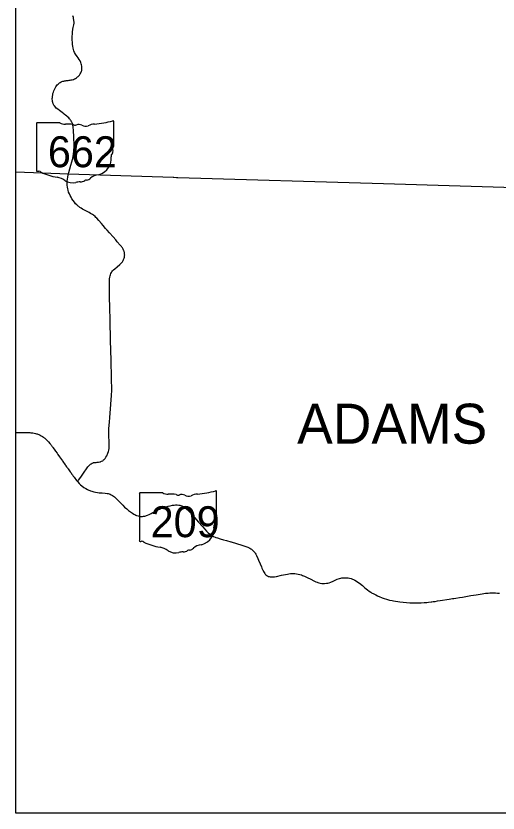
# Model space of a CAD drawing. Extents: x -12.1 to 34, y 0 to 22.
# Drawn here: x -12.146 to -10.219, y 10.977 to 14.162 of the extents above; entities that cross this region are included whole.
import ezdxf

# ---------------------------------------------------------------- set-up
doc = ezdxf.new("R2010")
doc.units = 0
for name, color, linetype in [('GM_X_State_Location', 7, 'Continuous'), ('GM_X_State_Route', 7, 'Continuous'), ('GM_X_State_Shield', 7, 'Continuous'), ('GM_X_Township', 7, 'Continuous'), ('GM_X_Township_Text', 7, 'Continuous'), ('SH_Text', 7, 'Continuous')]:
    doc.layers.add(name, color=color, linetype=linetype)

msp = doc.modelspace()

# ---------------------------------------------------------------- linework, layer by layer
at = {"layer": 'GM_X_State_Route'}
for points in [[(-11.9363, 13.5312), (-11.935, 13.5365), (-11.9307, 13.551), (-11.9263, 13.5655), (-11.9227, 13.579), (-11.9203, 13.5886), (-11.9195, 13.5922), (-11.9175, 13.602), (-11.9163, 13.6091), (-11.9159, 13.6119), (-11.9149, 13.6221), (-11.9144, 13.629), (-11.9142, 13.6325), (-11.914, 13.6406), (-11.9142, 13.6569), (-11.9148, 13.6675), (-11.9154, 13.6865), (-11.9161, 13.697), (-11.9166, 13.7085), (-11.9171, 13.7137), (-11.9178, 13.7202), (-11.9184, 13.7242), (-11.9192, 13.7279), (-11.9199, 13.7303), (-11.9207, 13.7324), (-11.9219, 13.7351), (-11.9229, 13.7372), (-11.9243, 13.7397), (-11.926, 13.7429), (-11.9277, 13.7454), (-11.9297, 13.748), (-11.9325, 13.7514), (-11.9355, 13.7548), (-11.9398, 13.7591), (-11.9434, 13.7622), (-11.9479, 13.7658), (-11.9517, 13.7686), (-11.955, 13.7712), (-11.9621, 13.7764), (-11.9724, 13.7838), (-11.9794, 13.7893), (-11.9849, 13.7941), (-11.9886, 13.7978), (-11.9913, 13.8012), (-11.993, 13.8034), (-11.9938, 13.8046), (-11.9949, 13.8062), (-11.9958, 13.8082), (-11.9969, 13.8105), (-11.9976, 13.8122), (-11.9985, 13.8149), (-11.9991, 13.8169), (-11.9998, 13.8203), (-12.0006, 13.825), (-12.0009, 13.8295), (-12.001, 13.8326), (-12.0007, 13.8361), (-12.0004, 13.8409), (-11.9995, 13.8466), (-11.9984, 13.8521), (-11.9968, 13.858), (-11.9951, 13.8632), (-11.9925, 13.8686), (-11.9897, 13.8741), (-11.9871, 13.8783), (-11.9838, 13.883), (-11.981, 13.8866), (-11.978, 13.8897), (-11.9763, 13.8913), (-11.9745, 13.8928), (-11.9719, 13.8948), (-11.9693, 13.8965), (-11.966, 13.8984), (-11.9625, 13.9), (-11.9584, 13.9013), (-11.9548, 13.9021), (-11.9519, 13.9028), (-11.9483, 13.9034), (-11.9449, 13.904), (-11.9415, 13.9044), (-11.9375, 13.9046), (-11.9336, 13.9051), (-11.9294, 13.9057), (-11.9251, 13.9065), (-11.921, 13.9074), (-11.9166, 13.9087), (-11.9121, 13.9108), (-11.9083, 13.9126), (-11.9049, 13.9147), (-11.9024, 13.9164), (-11.9, 13.9185), (-11.8974, 13.9207), (-11.8952, 13.9227), (-11.8929, 13.9254), (-11.8911, 13.928), (-11.8892, 13.9307), (-11.8869, 13.9348), (-11.8842, 13.9416), (-11.8834, 13.9447), (-11.8826, 13.9486), (-11.8824, 13.9506), (-11.8823, 13.9524), (-11.8823, 13.9569), (-11.8828, 13.9616), (-11.8837, 13.9663), (-11.8852, 13.9714), (-11.887, 13.9762), (-11.8898, 13.9824), (-11.8934, 13.9885), (-11.8979, 13.9951), (-11.902, 14.0006), (-11.9085, 14.0093), (-11.9123, 14.0155), (-11.9155, 14.0229), (-11.9169, 14.0276), (-11.9182, 14.0332), (-11.9193, 14.0411), (-11.9201, 14.0481), (-11.9207, 14.0566), (-11.9211, 14.0672), (-11.9211, 14.0805), (-11.9207, 14.0909), (-11.9202, 14.0972), (-11.9186, 14.1097), (-11.9173, 14.1162), (-11.9152, 14.1264), (-11.9142, 14.1336), (-11.914, 14.1371), (-11.9143, 14.1434), (-11.9145, 14.1458), (-11.9157, 14.1525), (-11.9169, 14.1565), (-11.919, 14.1632)], [(-11.9007, 12.3022), (-11.8997, 12.3032), (-11.898, 12.305), (-11.8965, 12.3068), (-11.8913, 12.3135), (-11.8847, 12.3232), (-11.8732, 12.3399), (-11.8638, 12.3532), (-11.8586, 12.3602), (-11.8552, 12.3643), (-11.8515, 12.368), (-11.8484, 12.3707), (-11.845, 12.3732), (-11.8413, 12.3753), (-11.838, 12.3768), (-11.8357, 12.3774), (-11.8341, 12.3777), (-11.8313, 12.3781), (-11.8284, 12.3785), (-11.8258, 12.3786), (-11.8213, 12.3788), (-11.8165, 12.3793), (-11.8104, 12.3804), (-11.8077, 12.3811), (-11.8064, 12.3816), (-11.8042, 12.3827), (-11.7996, 12.3852), (-11.798, 12.3862), (-11.7959, 12.388), (-11.7934, 12.39), (-11.792, 12.3914), (-11.7895, 12.3944), (-11.7864, 12.3995), (-11.7836, 12.404), (-11.7788, 12.4148), (-11.7767, 12.4213), (-11.7753, 12.4271), (-11.7742, 12.434), (-11.7737, 12.4413), (-11.7738, 12.4493), (-11.7742, 12.4617), (-11.7754, 12.4831), (-11.7753, 12.4955), (-11.7751, 12.5057), (-11.7748, 12.5144), (-11.7739, 12.5264), (-11.773, 12.5405), (-11.7716, 12.5558), (-11.77, 12.5766), (-11.7685, 12.5911), (-11.7652, 12.6297), (-11.7644, 12.6441), (-11.7638, 12.6523), (-11.7636, 12.6608), (-11.7636, 12.6666), (-11.7634, 12.6716), (-11.7633, 12.6784), (-11.7635, 12.6877), (-11.7637, 12.6935), (-11.7642, 12.708), (-11.7646, 12.7156), (-11.7649, 12.7261), (-11.7649, 12.7343), (-11.7649, 12.7447), (-11.7652, 12.7574), (-11.7653, 12.772), (-11.7663, 12.7953), (-11.7671, 12.8174), (-11.7675, 12.8314), (-11.7679, 12.8611), (-11.7681, 12.8762), (-11.7684, 12.8931), (-11.7691, 12.9186), (-11.7695, 12.932), (-11.7698, 12.9442), (-11.7699, 12.9488), (-11.7701, 12.9558), (-11.7703, 12.9634), (-11.7707, 12.9797), (-11.7713, 13.0035), (-11.7719, 13.0315), (-11.7721, 13.0489), (-11.7725, 13.0693), (-11.7729, 13.0862), (-11.773, 13.0966), (-11.7727, 13.106), (-11.7722, 13.1124), (-11.7714, 13.1188), (-11.7702, 13.124), (-11.7687, 13.1284), (-11.7669, 13.1328), (-11.765, 13.1365), (-11.7628, 13.1399), (-11.7597, 13.1436), (-11.7563, 13.1474), (-11.7517, 13.1517), (-11.7421, 13.1602), (-11.7311, 13.1697), (-11.7244, 13.1761), (-11.7206, 13.1804), (-11.7181, 13.1849), (-11.7162, 13.1885), (-11.715, 13.1912), (-11.7141, 13.1944), (-11.713, 13.1979), (-11.7124, 13.2008), (-11.7118, 13.2046), (-11.7117, 13.2074), (-11.7118, 13.2097), (-11.7122, 13.2134), (-11.7127, 13.2171), (-11.7134, 13.2196), (-11.7141, 13.2221), (-11.7149, 13.2241), (-11.7159, 13.2267), (-11.7177, 13.2303), (-11.7192, 13.2329), (-11.7206, 13.2351), (-11.7227, 13.2381), (-11.7245, 13.2405), (-11.7292, 13.2461), (-11.7411, 13.26), (-11.7477, 13.2679), (-11.7578, 13.2792), (-11.7722, 13.2954), (-11.7818, 13.3061), (-11.7878, 13.3129), (-11.7976, 13.3244), (-11.8046, 13.3324), (-11.8154, 13.3451), (-11.823, 13.3536), (-11.8269, 13.3575), (-11.83, 13.3602), (-11.8366, 13.3659), (-11.8401, 13.3686), (-11.8427, 13.3705), (-11.8477, 13.3735), (-11.8538, 13.3768), (-11.8692, 13.3846), (-11.8805, 13.3907), (-11.8853, 13.3935), (-11.8883, 13.3955), (-11.891, 13.3973), (-11.8932, 13.3989), (-11.8953, 13.4005), (-11.8977, 13.4025), (-11.8995, 13.404), (-11.9008, 13.4052), (-11.9031, 13.4075), (-11.9077, 13.412), (-11.9127, 13.418), (-11.9178, 13.4249), (-11.9223, 13.4313), (-11.9262, 13.4376), (-11.9301, 13.4448), (-11.9328, 13.4508), (-11.9358, 13.4583), (-11.938, 13.4656), (-11.9391, 13.471), (-11.9403, 13.4786), (-11.9409, 13.4861), (-11.9411, 13.4937), (-11.9409, 13.5018), (-11.9402, 13.5098), (-11.9391, 13.5179), (-11.9374, 13.527), (-11.9363, 13.5312)], [(-12.1463, 12.4978), (-12.1443, 12.4978), (-12.1414, 12.4978), (-12.1338, 12.4978), (-12.128, 12.4978), (-12.1216, 12.4979), (-12.1159, 12.4979), (-12.1095, 12.4978), (-12.1066, 12.4977), (-12.0996, 12.4976), (-12.091, 12.4973), (-12.0864, 12.4969), (-12.0818, 12.4964), (-12.0785, 12.4959), (-12.0729, 12.4948), (-12.0678, 12.4936), (-12.0644, 12.4927), (-12.062, 12.4919), (-12.059, 12.4907), (-12.0553, 12.4893), (-12.0495, 12.4866), (-12.0455, 12.4846), (-12.0407, 12.4819), (-12.0366, 12.4795), (-12.0331, 12.4771), (-12.0308, 12.4752), (-12.0263, 12.4716), (-12.0209, 12.4664), (-12.0183, 12.4635), (-12.0157, 12.4604), (-12.0103, 12.4536), (-12.0075, 12.4499), (-12.0055, 12.4471), (-12.0044, 12.4457), (-12.003, 12.4439), (-12.0005, 12.4407), (-11.9987, 12.4384), (-11.9939, 12.4318), (-11.9876, 12.4228), (-11.9819, 12.4147), (-11.9789, 12.4105), (-11.972, 12.4004), (-11.9644, 12.3894), (-11.9606, 12.3842), (-11.9589, 12.3819), (-11.9562, 12.3781), (-11.952, 12.3726), (-11.9496, 12.3692), (-11.9473, 12.3659), (-11.9467, 12.365), (-11.9436, 12.3608), (-11.9406, 12.3565), (-11.9386, 12.3536), (-11.9379, 12.3527), (-11.9352, 12.349), (-11.9323, 12.3447), (-11.93, 12.3413), (-11.9262, 12.3362), (-11.9239, 12.3328), (-11.9216, 12.3295), (-11.9209, 12.3285), (-11.9175, 12.3238), (-11.9141, 12.3191), (-11.911, 12.3149), (-11.9074, 12.3103), (-11.9045, 12.3066), (-11.9007, 12.3022), (-11.8992, 12.3004), (-11.8938, 12.2943), (-11.8887, 12.2891), (-11.8831, 12.2842), (-11.8744, 12.2783), (-11.8696, 12.2753), (-11.867, 12.2737), (-11.8608, 12.2703), (-11.8555, 12.2677), (-11.851, 12.2658), (-11.848, 12.2646), (-11.843, 12.2628), (-11.8356, 12.2608), (-11.8279, 12.2589), (-11.8198, 12.2576), (-11.8137, 12.257), (-11.8022, 12.2562), (-11.7895, 12.2557), (-11.7823, 12.2547), (-11.7783, 12.254), (-11.7742, 12.2528), (-11.7703, 12.2512), (-11.7655, 12.2492), (-11.7606, 12.2467), (-11.7564, 12.2439), (-11.7523, 12.2408), (-11.7466, 12.2359), (-11.7425, 12.2317), (-11.7385, 12.2277), (-11.727, 12.2153), (-11.7194, 12.2072), (-11.7118, 12.1999), (-11.7035, 12.1926), (-11.6958, 12.1864), (-11.6878, 12.1804), (-11.6806, 12.1755), (-11.6747, 12.1721), (-11.6713, 12.1701), (-11.6672, 12.1682), (-11.664, 12.1668), (-11.6584, 12.1649), (-11.6534, 12.1636), (-11.6482, 12.1628), (-11.6438, 12.1625), (-11.6403, 12.1626), (-11.6362, 12.1631), (-11.6312, 12.164), (-11.6275, 12.1651), (-11.6244, 12.1662), (-11.6207, 12.1678), (-11.6144, 12.1707), (-11.6063, 12.1747), (-11.5838, 12.187), (-11.5731, 12.1921), (-11.5654, 12.1954), (-11.5628, 12.1964), (-11.5563, 12.1985), (-11.5468, 12.2014), (-11.5382, 12.2035), (-11.5303, 12.2053), (-11.5199, 12.2072), (-11.5136, 12.208), (-11.5081, 12.2084), (-11.5019, 12.2084), (-11.4959, 12.208), (-11.4918, 12.2073), (-11.4873, 12.206), (-11.4831, 12.2043), (-11.4784, 12.2019), (-11.4736, 12.1992), (-11.4697, 12.1964), (-11.4655, 12.1929), (-11.4542, 12.1825), (-11.4488, 12.177), (-11.4424, 12.1698), (-11.4326, 12.1587), (-11.4168, 12.1402), (-11.4013, 12.122), (-11.3919, 12.1114), (-11.3843, 12.1031), (-11.3781, 12.0972), (-11.3726, 12.0926), (-11.3676, 12.0889), (-11.3638, 12.0864), (-11.3569, 12.0826), (-11.3505, 12.0799), (-11.3468, 12.0786), (-11.3406, 12.0764), (-11.3299, 12.0731), (-11.317, 12.0695), (-11.3041, 12.0659), (-11.2873, 12.0612), (-11.2863, 12.0609), (-11.2649, 12.0546), (-11.2432, 12.0479), (-11.2312, 12.0438), (-11.2238, 12.0409), (-11.2195, 12.0394), (-11.2167, 12.0382), (-11.2109, 12.0353), (-11.2071, 12.0331), (-11.2044, 12.0313), (-11.2006, 12.0282), (-11.1981, 12.0256), (-11.1948, 12.0217), (-11.1919, 12.0178), (-11.1903, 12.0154), (-11.1881, 12.0117), (-11.1851, 12.006), (-11.1796, 11.9945), (-11.1763, 11.9871), (-11.1706, 11.9731), (-11.1653, 11.9605), (-11.1632, 11.9557), (-11.1613, 11.951), (-11.1601, 11.9485), (-11.157, 11.9427), (-11.1546, 11.9386), (-11.152, 11.9347), (-11.1501, 11.9322), (-11.1483, 11.9302), (-11.1469, 11.929), (-11.1432, 11.9263), (-11.1416, 11.9251), (-11.1396, 11.924), (-11.1377, 11.9231), (-11.1347, 11.9221), (-11.1304, 11.9212), (-11.1258, 11.9207), (-11.1219, 11.9207), (-11.1195, 11.9209), (-11.1153, 11.9214), (-11.1126, 11.9218), (-11.1055, 11.9231), (-11.0848, 11.9276), (-11.0684, 11.9308), (-11.0614, 11.9321), (-11.0551, 11.9332), (-11.0484, 11.934), (-11.0451, 11.9343), (-11.0406, 11.9344), (-11.0361, 11.9344), (-11.0311, 11.9342), (-11.0256, 11.9336), (-11.0184, 11.9323), (-11.0119, 11.9308), (-11.0056, 11.929), (-11.0003, 11.9271), (-10.9967, 11.9256), (-10.9925, 11.9237), (-10.9876, 11.9214), (-10.982, 11.9188), (-10.9675, 11.9113), (-10.9563, 11.9053), (-10.9471, 11.9012), (-10.9419, 11.8993), (-10.9391, 11.8984), (-10.936, 11.8974), (-10.9297, 11.896), (-10.9238, 11.8951), (-10.9186, 11.8947), (-10.9132, 11.8946), (-10.9056, 11.8953), (-10.8996, 11.8963), (-10.8948, 11.8977), (-10.8881, 11.9002), (-10.8783, 11.9043), (-10.8704, 11.9079), (-10.8619, 11.9113), (-10.8537, 11.9141), (-10.8471, 11.9158), (-10.8434, 11.9166), (-10.84, 11.9171), (-10.8362, 11.9175), (-10.8296, 11.9177), (-10.8244, 11.9174), (-10.8185, 11.9168), (-10.813, 11.9159), (-10.8069, 11.9142), (-10.8015, 11.9124), (-10.7972, 11.9106), (-10.7915, 11.9078), (-10.7855, 11.9043), (-10.7793, 11.9002), (-10.7733, 11.8956), (-10.7618, 11.8861), (-10.7517, 11.8778), (-10.7416, 11.8694), (-10.7343, 11.8639), (-10.7272, 11.8593), (-10.7246, 11.8577), (-10.716, 11.8529), (-10.7137, 11.8517), (-10.708, 11.8487), (-10.7017, 11.8457), (-10.6985, 11.8444), (-10.6948, 11.8427), (-10.6831, 11.8377), (-10.6739, 11.8343), (-10.6648, 11.8315), (-10.6566, 11.8292), (-10.6535, 11.8284), (-10.6432, 11.8262), (-10.6369, 11.825), (-10.6116, 11.8214), (-10.5988, 11.8198), (-10.585, 11.8186), (-10.5713, 11.8176), (-10.5591, 11.8172), (-10.5539, 11.8171), (-10.551, 11.8171), (-10.5455, 11.8169), (-10.54, 11.817), (-10.5351, 11.8171), (-10.5272, 11.8174), (-10.5145, 11.8181), (-10.5087, 11.8185), (-10.5034, 11.8191), (-10.498, 11.8197), (-10.4868, 11.8209), (-10.4834, 11.8214), (-10.4784, 11.8221), (-10.471, 11.8232), (-10.4611, 11.8247), (-10.4513, 11.8263), (-10.4413, 11.8279), (-10.4235, 11.8308), (-10.4145, 11.8321), (-10.402, 11.834), (-10.3964, 11.835), (-10.3879, 11.8363), (-10.3729, 11.8384), (-10.362, 11.8401), (-10.3482, 11.8427), (-10.3277, 11.8465), (-10.307, 11.8498), (-10.2823, 11.8537), (-10.269, 11.8553), (-10.2592, 11.8565), (-10.2523, 11.8571), (-10.2477, 11.8573), (-10.2381, 11.8572), (-10.2291, 11.8568), (-10.2216, 11.8564), (-10.213, 11.8554)]]:
    msp.add_lwpolyline(points, dxfattribs=at)
at = {"layer": 'GM_X_State_Shield'}
for p, q in [((-12.0645, 13.7322), (-12.0645, 13.5446)), ((-11.971, 13.7354), (-12.0615, 13.7354)), ((-11.7555, 13.642), (-11.7555, 13.7401)), ((-11.7556, 13.642), (-11.7555, 13.642)), ((-11.3442, 12.1636), (-11.3442, 12.2617)), ((-11.6531, 12.2539), (-11.6531, 12.0662)), ((-11.5596, 12.2571), (-11.6501, 12.2571)), ((-11.3442, 12.1636), (-11.3442, 12.1636))]:
    msp.add_line(p, q, dxfattribs=at)
for centre, major_axis, start_param, end_param in [((-12.061, 13.7326), (0.00358, 0), 1.712693, 3.28349), ((-11.9494, 13.7572), (0.0347, 0), 4.042523, 4.731795), ((-11.9379, 13.6301), (0.1246, 0), 1.404758, 1.657858), ((-11.9096, 13.7336), (0.01, 0), 3.836095, 5.185415), ((-11.8949, 13.7119), (0.0208, 0), 0.950623, 2.079405), ((-11.8238, 13.6781), (0.0659, 0), 1.699011, 2.107814), ((-11.8656, 13.9912), (0.3277, 0), 4.814394, 5.042369), ((-11.759, 13.7405), (0.00344, 0), 6.141152, 7.989035), ((-11.868, 13.7417), (0.0251, 0), 4.081561, 5.145723), ((-11.7563, 13.6348), (0.00532, 0), 1.883978, 3.671073), ((-11.7902, 13.6223), (0.032, 0), 5.934695, 6.695948), ((-11.7592, 13.6416), (0.00368, 0), 5.05454, 6.418171), ((-11.7432, 13.6009), (0.0232, 0), 2.387724, 3.262537), ((-11.8472, 13.5884), (0.082, 0), 5.101752, 6.440018), ((-12.0609, 13.5442), (0.00361, 0), 3.00124, 4.508301), ((-12.0604, 13.5634), (0.0276, 0), 4.665946, 4.897461), ((-12.0548, 13.5338), (0.00994, 0), 0.519207, 1.627899), ((-11.9293, 13.7023), (0.2366, 0), 4.195997, 4.488961), ((-11.9998, 13.4603), (0.074, 0), 0.823519, 1.323587), ((-11.9198, 13.5329), (0.047, 0), 4.026481, 4.996735), ((-11.8892, 13.5188), (0.025, 0), 4.691044, 5.507374), ((-11.8666, 13.5006), (0.00705, 0), 1.147584, 2.315152), ((-11.8696, 13.5264), (0.0265, 0), 4.937069, 5.64225), ((-11.8127, 13.4919), (0.0449, 0), 1.647645, 2.488434), ((-11.8926, 13.468), (0.0386, 0), 1.495662, 1.94098), ((-11.4542, 12.5129), (0.3277, 0), 4.814394, 5.042369), ((-11.3476, 12.2621), (0.00344, 0), 6.141152, 7.989035), ((-11.6496, 12.2543), (0.00358, 0), 1.712693, 3.28349), ((-11.5381, 12.2789), (0.0347, 0), 4.042523, 4.731795), ((-11.5266, 12.1518), (0.1246, 0), 1.404758, 1.657858), ((-11.4983, 12.2552), (0.01, 0), 3.836095, 5.185415), ((-11.4836, 12.2335), (0.0208, 0), 0.950623, 2.079405), ((-11.4567, 12.2633), (0.0251, 0), 4.081561, 5.145723), ((-11.4124, 12.1998), (0.0659, 0), 1.699011, 2.107814), ((-11.3318, 12.1225), (0.0232, 0), 2.387724, 3.262537), ((-11.345, 12.1564), (0.00532, 0), 1.883978, 3.671073), ((-11.3788, 12.144), (0.032, 0), 5.934695, 6.695948), ((-11.3478, 12.1632), (0.00368, 0), 5.05454, 6.418171), ((-11.4359, 12.11), (0.082, 0), 5.101752, 6.440018), ((-11.6496, 12.0658), (0.00361, 0), 3.00124, 4.508301), ((-11.649, 12.085), (0.0276, 0), 4.665946, 4.897461), ((-11.6434, 12.0554), (0.00994, 0), 0.519207, 1.627899), ((-11.5179, 12.224), (0.2366, 0), 4.195997, 4.488961), ((-11.5885, 11.982), (0.074, 0), 0.823519, 1.323587), ((-11.4013, 12.0136), (0.0449, 0), 1.647645, 2.488434), ((-11.5084, 12.0545), (0.047, 0), 4.026481, 4.996735), ((-11.4813, 11.9896), (0.0386, 0), 1.495662, 1.94098), ((-11.4778, 12.0404), (0.025, 0), 4.691044, 5.507374), ((-11.4552, 12.0223), (0.00705, 0), 1.147584, 2.315152), ((-11.4582, 12.0481), (0.0265, 0), 4.937069, 5.64225)]:
    msp.add_ellipse(centre, major_axis=major_axis, ratio=0.8, start_param=start_param, end_param=end_param, dxfattribs=at)
at = {"layer": 'GM_X_Township'}
msp.add_lwpolyline([(-12.1463, 13.5392), (-11.9365, 13.5317), (-11.5173, 13.5177), (-11.515, 13.5176), (-11.5042, 13.517), (-11.4993, 13.5169), (-10.6773, 13.4926), (-9.407, 13.4542), (-8.9332, 13.439)], dxfattribs=at)
at = {"layer": 'SH_Text'}
msp.add_lwpolyline([(-12.1463, 20.3063), (-4.4383, 20.3063), (-4.4383, 10.9773), (-12.1463, 10.9773)], close=True, dxfattribs=at)

# ---------------------------------------------------------------- texts
at = {"layer": 'GM_X_State_Location'}
msp.add_text('662', height=0.000178, rotation=0, dxfattribs=at).set_placement((-11.9762, 13.613))
for s in ['s', 'r']:
    msp.add_text(s, height=0.000178, dxfattribs=at).set_placement((-11.9135, 13.6259))
at = {"layer": 'GM_X_State_Shield'}
for s, p in [('662', (-12.0186, 13.5578)), ('209', (-11.6077, 12.0795))]:
    msp.add_text(s, height=0.1236, dxfattribs=at).set_placement(p)
at = {"layer": 'GM_X_Township_Text'}
msp.add_text('ADAMS', height=0.1598, rotation=0, dxfattribs=at).set_placement((-11.0224, 12.4531))

doc.saveas('drawing.dxf')
